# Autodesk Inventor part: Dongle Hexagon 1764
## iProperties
Created: 2010-01
Part Number: Dongle Hexagon 1764
Document SubType Name: Modeling
Designer: jgehrig
Density: 1 g/cm^3
Author: jgehrig
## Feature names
1. Extrusion1
